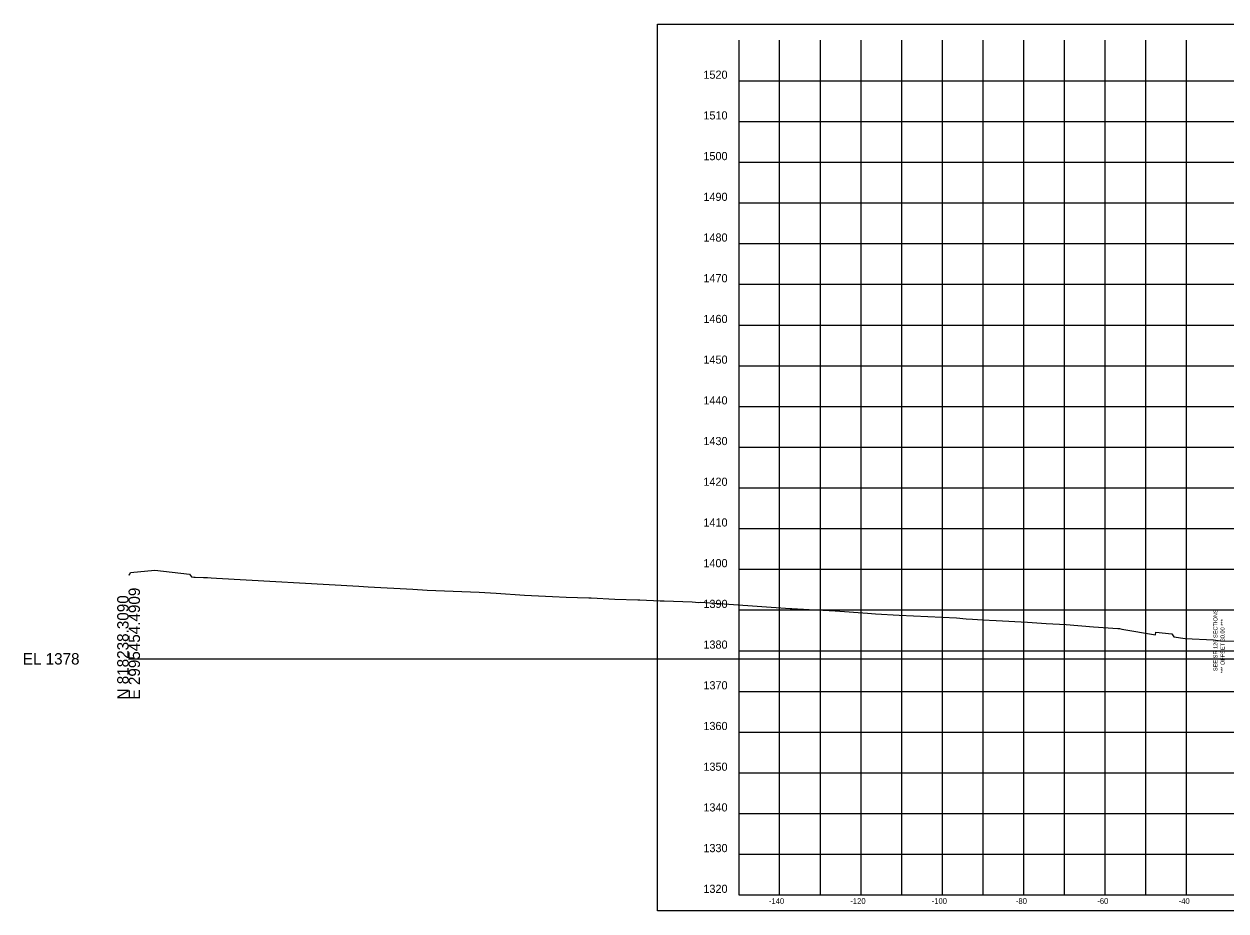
# Model space of a CAD drawing. Extents: x -26 to 603, y -10 to 2564.
# Drawn here: x -25.7 to 269.7, y 438.1 to 655.9 of the extents above; entities that cross this region are included whole.
import ezdxf

# ---------------------------------------------------------------- set-up
doc = ezdxf.new("R2010")
doc.units = 0
for name, color, linetype in [('DESIGN - SHEET - Corner Text', 7, 'Continuous'), ('DESIGN - SHEET - Light Grid', 7, 'Continuous'), ('DESIGN - SHEET - Linework', 7, 'Continuous'), ('DESIGN - SHEET - Plot Shape', 7, 'Continuous'), ('DESIGN - TYPICAL - Text', 7, 'Continuous'), ('SURVEY - GROUND - Top of Ground', 7, 'Continuous')]:
    doc.layers.add(name, color=color, linetype=linetype)

msp = doc.modelspace()

# ---------------------------------------------------------------- linework, layer by layer
at = {"layer": 'DESIGN - SHEET - Light Grid'}
msp.add_line((0, 500), (300, 500), dxfattribs=at)
at = {"layer": 'DESIGN - SHEET - Linework'}
for p, q in [((160, 442), (160, 652)), ((170, 442), (170, 652)), ((180, 442), (180, 652)), ((190, 442), (190, 652)), ((200, 442), (200, 652)), ((210, 442), (210, 652)), ((220, 442), (220, 652)), ((230, 442), (230, 652)), ((240, 442), (240, 652)), ((250, 442), (250, 652)), ((260, 442), (260, 652)), ((150, 642), (450, 642)), ((150, 632), (450, 632)), ((150, 622), (450, 622)), ((150, 612), (450, 612)), ((150, 602), (450, 602)), ((150, 592), (450, 592)), ((150, 582), (450, 582)), ((150, 572), (450, 572)), ((150, 562), (450, 562)), ((150, 552), (450, 552)), ((150, 542), (450, 542)), ((150, 532), (450, 532)), ((150, 522), (450, 522)), ((150, 512), (450, 512)), ((150, 502), (450, 502)), ((150, 492), (450, 492)), ((150, 482), (450, 482)), ((150, 472), (450, 472)), ((150, 462), (450, 462)), ((150, 452), (450, 452))]:
    msp.add_line(p, q, dxfattribs=at)
msp.add_lwpolyline([(150, 652), (150, 442), (450, 442), (450, 652)], dxfattribs=at)
at = {"layer": 'DESIGN - SHEET - Plot Shape'}
msp.add_lwpolyline([(130, 655.94), (470, 655.94), (470, 438.06), (130, 438.06)], close=True, dxfattribs=at)
at = {"layer": 'SURVEY - GROUND - Top of Ground'}
msp.add_lwpolyline([(0, 520.68), (0.23, 520.67), (0.51, 521.2), (6.44, 521.81), (14.94, 520.81), (15.5, 520.11), (16.04, 520.09), (16.36, 520.08), (18.39, 520.01), (18.83, 519.98), (19.43, 519.95), (20.28, 519.9), (21.6, 519.83), (56.57, 517.83), (58.88, 517.7), (69.87, 517.11), (73.36, 516.9), (86.19, 516.37), (90.36, 516.12), (97.29, 515.61), (104.19, 515.34), (107.57, 515.11), (113.12, 514.97), (113.64, 514.96), (119.47, 514.64), (125.17, 514.5), (125.61, 514.47), (130.63, 514.28), (131.61, 514.23), (138.46, 513.97), (140.12, 513.87), (140.54, 513.88), (162.55, 512.37), (163, 512.35), (168.75, 512.01), (170.63, 511.92), (173.68, 511.76), (181.62, 511.18), (183.58, 511.06), (189.37, 510.69), (203.45, 510.04), (205.84, 509.85), (207.4, 509.72), (209.84, 509.59), (213.18, 509.44), (220.87, 508.98), (225.47, 508.69), (230.39, 508.42), (237.13, 507.86), (243.14, 507.44), (243.49, 507.42), (244.08, 507.32), (252.37, 505.91), (252.47, 506.56), (256.41, 506.12), (256.87, 505.39), (259.62, 504.97), (266.6, 504.66), (268.34, 504.45), (272.97, 504.33)], dxfattribs=at)

# ---------------------------------------------------------------- texts
at = {"layer": 'DESIGN - SHEET - Corner Text'}
for s, height, p in [('1520', 2, (141.25, 642.5)), ('1510', 2, (141.25, 632.5)), ('1500', 2, (141.25, 622.5)), ('1490', 2, (141.25, 612.5)), ('1480', 2, (141.25, 602.5)), ('1470', 2, (141.25, 592.5)), ('1460', 2, (141.25, 582.5)), ('1450', 2, (141.25, 572.5)), ('1440', 2, (141.25, 562.5)), ('1430', 2, (141.25, 552.5)), ('1420', 2, (141.25, 542.5)), ('1410', 2, (141.25, 532.5)), ('1400', 2, (141.25, 522.5)), ('1390', 2, (141.25, 512.5)), ('1380', 2, (141.25, 502.5)), ('1370', 2, (141.25, 492.5)), ('1360', 2, (141.25, 482.5)), ('1350', 2, (141.25, 472.5)), ('1340', 2, (141.25, 462.5)), ('1330', 2, (141.25, 452.5)), ('1320', 2, (141.25, 442.5)), ('-140', 1.4, (157.37, 439.8)), ('-120', 1.4, (177.37, 439.8)), ('-100', 1.4, (197.37, 439.8)), ('-80', 1.4, (218.06, 439.8)), ('-60', 1.4, (238.06, 439.8)), ('-40', 1.4, (258.06, 439.8))]:
    msp.add_text(s, height=height, dxfattribs=at).set_placement(p)
at = {"layer": 'DESIGN - SHEET - Light Grid'}
for s, p in [('E 2995454.4909', (2.8, 490)), ('N 818238.3090', (0, 490))]:
    msp.add_text(s, height=2.8, rotation=90, dxfattribs=at).set_placement(p)
msp.add_text('EL 1378', height=2.8, dxfattribs=at).set_placement((-26, 498.6))
at = {"layer": 'DESIGN - TYPICAL - Text'}
for s, p in [('SEE SR 126 SECTIONS', (267.59, 496.97)), ('*** OFFSET 30.00 ***', (269.34, 496.46))]:
    msp.add_text(s, height=1, rotation=90, dxfattribs=at).set_placement(p)

doc.saveas('drawing.dxf')
